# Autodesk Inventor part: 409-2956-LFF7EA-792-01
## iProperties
Shininess: 64.0
Angle Display Precision: 2
Document Length Units: 11272
Document Angle Units: 11279
Document Time Units: 11290
Document Mass Units: 11286
Document Length Units Precision: 3
Document Angle Units Precision: 2
Compacted: True
Created: 2002-04
Part Number: 409-2956-LFF7EA-792-01
Description: DISCHARGE PIPE STAND ANGLE
Document SubType Name: Modeling
Designer: S. Boerckel
Mass: 4272.04 g
Surface Area: 1782.52 cm^2
Volume: 544.209 cm^3
Density: 7.85 g/cm^3
Cost Center: 2 x 2 x 1/4 ANGLE
Material: ASTM A36
Engineer: S. Boerckel
Density: 0.0
Volumn: 0.0
Area: 0.0
PropertySet Name: Model Information
Control State: 0
Master: False
Checked Out: False
length: 35.503 in
SMR: =<COST CENTER> - <MATERIAL>
Author: S. Boerckel
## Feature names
1. Extrusion1
